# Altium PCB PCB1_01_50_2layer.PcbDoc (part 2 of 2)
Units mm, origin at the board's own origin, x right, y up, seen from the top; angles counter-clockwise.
Board outline 28.45 x 21.72 mm, 2 copper layers (Top Layer, Bottom Layer); 0 components, 1 nets, 10 pads, 74 vias.
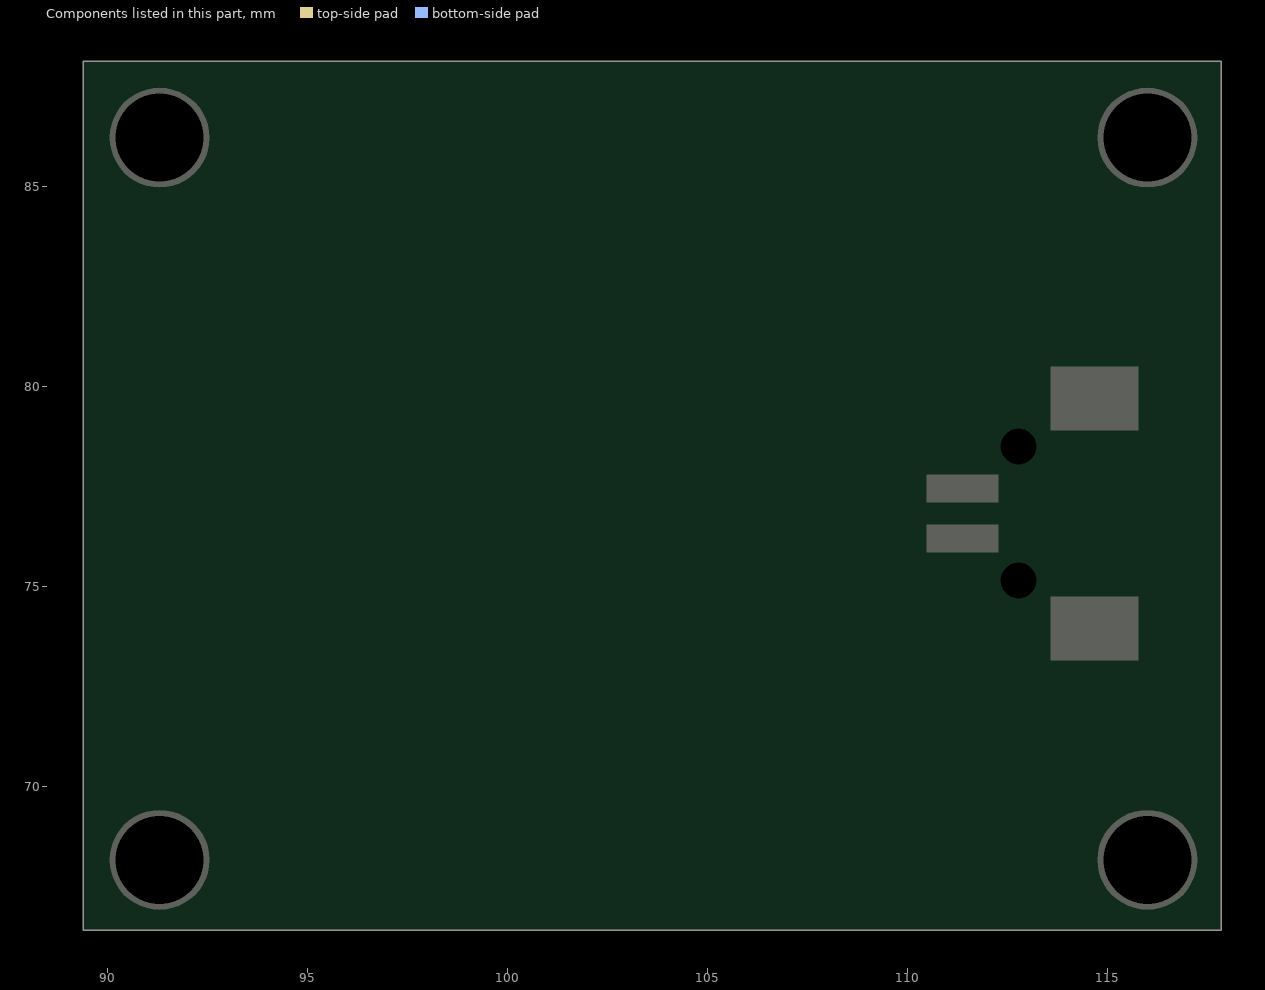
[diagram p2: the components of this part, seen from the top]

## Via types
v1: diameter 0.5, hole 0.3, Top Layer to Bottom Layer, tented both sides, 67 vias
v2: diameter 1, hole 0.5, Top Layer to Bottom Layer, 7 vias

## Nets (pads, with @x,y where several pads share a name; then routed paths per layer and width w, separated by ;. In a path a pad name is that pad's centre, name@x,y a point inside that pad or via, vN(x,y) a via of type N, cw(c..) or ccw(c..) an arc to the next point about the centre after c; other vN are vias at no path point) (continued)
copper on no net: (continued)
  Bottom Layer w0.1: 98.93,82.919 cw(c100.29,77.385) 100.643,83.073 cw(c100.265,77.417) 102.321,82.699 cw(c100.207,77.234) 103.819,81.848 cw(c100.429,77.508) 104.991,80.593 cw(c100.185,77.352) 105.731,79.038 cw(c100.25,77.359) 105.982,77.336 cw(c100.268,77.406) 104.93,74.101 cw(c100.411,77.273) 103.737,72.866 cw(c100.317,77.429) 102.22,72.053 cw(c100.294,77.457) 100.53,71.726 cw(c100.315,77.169) 98.824,71.929 cw(c100.397,77.486) 97.255,72.64 cw(c100.257,77.291) 95.974,73.785 cw(c100.333,77.32) 95.108,75.272 cw(c100.253,77.331) 94.873,78.661 cw(c100.419,77.267) 95.54,80.249 cw(c100.266,77.374) 96.65,81.561 cw(c100.247,77.355) 98.115,82.462 cw(c100.275,77.387) 101.498,82.765 cw(c100.214,77.249) 103.096,82.124 cw(c100.304,77.377) 104.424,81.032 cw(c100.313,77.421) 105.342,79.578 cw(c100.323,77.383) 105.671,76.198 cw(c100.195,77.443) 105.036,74.598 cw(c100.319,77.356) 103.946,73.268 cw(c100.363,77.347) 102.491,72.353 cw(c100.328,77.332) 99.11,72.041 ; 98.93,82.919 ccw(c100.322,77.204) 97.334,82.271 ccw(c100.145,77.496) 96.007,81.18 ccw(c100.39,77.284) 95.064,79.739 ccw(c100.332,77.298) 94.58,78.088 ccw(c100.164,77.34) 94.614,76.37 ccw(c100.366,77.349) 96.14,73.327 ccw(c100.327,77.378) 97.505,72.28 ccw(c100.387,77.462) 99.116,71.671 ccw(c100.326,77.324) 102.505,71.969 ccw(c100.34,77.391) 103.991,72.836 ccw(c100.383,77.298) 105.151,74.105 ccw(c100.277,77.404) 106.162,77.356 ccw(c100.249,77.358) 105.913,79.058 ccw(c100.173,77.347) 105.189,80.621 ccw(c100.446,77.522) 104.042,81.9 ccw(c100.212,77.242) 102.568,82.793 ccw(c100.25,77.362) 100.904,83.231 ccw(c100.285,77.464) 99.187,83.159 ccw(c100.289,77.299) 96.159,81.599 ccw(c100.324,77.331) 95.114,80.232 ccw(c100.412,77.269) 94.495,78.625 ccw(c100.249,77.332) 94.739,75.23 ccw(c100.366,77.336) 95.567,73.721 ccw(c100.203,77.236) 96.796,72.519 ccw(c100.363,77.421) 100.004,71.37 ccw(c100.311,77.335) 101.717,71.53 ccw(c100.276,77.523) 103.32,72.163 ccw(c100.454,77.224) 104.674,73.221 ccw(c100.238,77.413) 105.668,74.627 ccw(c100.214,77.438) 106.234,76.253 ccw(c100.523,77.372) 106.312,77.97 ccw(c100.151,77.338) 105.899,79.643 ccw(c100.259,77.392) 105.041,81.135 ccw(c100.384,77.463) 103.792,82.316 ccw(c100.241,77.299) 100.573,83.437 ccw(c100.293,77.376) 98.86,83.272 ccw(c100.327,77.189) 97.256,82.641 ccw(c100.15,77.49) 95.896,81.59 ccw(c100.356,77.309) 94.888,80.194 ccw(c100.403,77.272) 94.299,78.576 ccw(c100.253,77.333) 94.566,75.179 ccw(c100.376,77.34) 95.384,73.664 ccw(c100.182,77.216) 96.595,72.444 ccw(c100.403,77.497) 98.1,71.604 ccw(c100.345,77.32) 99.774,71.206 ccw(c100.315,77.265) 101.491,71.296 ccw(c100.308,77.43) 104.536,72.832 ccw(c100.308,77.359) 105.619,74.17 ccw(c100.162,77.459) 106.301,75.753 ccw(c100.505,77.371) 106.522,77.457 ccw(c100.234,77.354) 106.258,79.159 ccw(c100.157,77.342) 105.547,80.728 ccw(c100.334,77.426) 103,82.992 ccw(c100.225,77.285) 101.363,83.528 ccw(c100.287,77.583) 99.645,83.59 ccw(c100.323,77.203) 97.971,83.18 ccw(c100.275,77.298) 96.469,82.339 ccw(c100.166,77.471) 95.259,81.117 ccw(c100.445,77.253) 94.423,79.61 ccw(c100.268,77.312) 94.019,77.937 ccw(c100.189,77.343) 94.093,76.219 ccw(c100.393,77.359) 95.574,73.144 ccw(c100.273,77.315) 96.881,72.026 ccw(c100.354,77.392) 100.137,71.004 ccw(c100.306,77.36) 101.848,71.191 ccw(c100.272,77.534) 103.452,71.824 ccw(c100.45,77.229) 104.824,72.86 ccw(c100.268,77.389) 105.864,74.232 ccw(c100.169,77.456) 106.508,75.831 ccw(c100.531,77.369) 106.7,77.539 ccw(c100.221,77.351) 106.422,79.239 ccw(c100.153,77.341) 105.709,80.808 ccw(c100.345,77.437) 103.185,83.101 ccw(c100.215,77.259) 101.559,83.673 ccw(c100.278,77.422) 98.157,83.44 ccw(c100.302,77.244) 96.617,82.667 ccw(c100.119,77.523) 95.343,81.513 ccw(c100.417,77.27) 94.419,80.058 ccw(c100.365,77.284) 93.902,78.415 ccw(c100.066,77.344) 93.843,76.697 ccw(c100.457,77.38) 94.241,75.02 ccw(c100.384,77.343) 95.057,73.502 ccw(c100.154,77.19) 96.246,72.26 ccw(c100.399,77.491) 97.722,71.371 ccw(c100.366,77.393) 99.376,70.891 ccw(c100.315,77.146) 101.096,70.87 ccw(c100.275,77.527) 102.765,71.299 ccw(c100.327,77.42) 104.268,72.14 ccw(c100.455,77.224) 105.492,73.348 ccw(c100.159,77.461) 106.361,74.837 ccw(c100.282,77.418) 106.822,76.496 ccw(c100.499,77.372) 106.826,78.216 ccw(c100.126,77.329) 106.384,79.882 ccw(c100.247,77.388) 105.534,81.38 ccw(c100.431,77.508) 104.32,82.598 ccw(c100.197,77.213) 102.829,83.463 ccw(c100.24,77.339) 101.17,83.923 ccw(c100.287,77.559) 99.45,83.929 ccw(c100.329,77.182) 97.782,83.492 ccw(c100.274,77.297) 96.281,82.648 ccw(c100.143,77.496) 95.055,81.442 ccw(c100.443,77.255) 94.177,79.958 ccw(c100.334,77.292) 93.702,78.303 ccw(c100.08,77.344) 93.675,76.583 ccw(c100.469,77.384) 94.091,74.91 ccw(c100.382,77.341) 94.912,73.396 ccw(c100.144,77.182) 96.096,72.149 ccw(c100.398,77.489) 97.564,71.245 ccw(c100.375,77.418) 99.21,70.736 ccw(c100.313,77.108) 100.928,70.671 ccw(c100.279,77.508) 102.61,71.047 ccw(c100.302,77.469) 104.145,71.83 ccw(c100.494,77.18) 105.424,72.98 ccw(c100.191,77.441) 106.369,74.421 ccw(c100.205,77.444) 106.928,76.051 ccw(c100.384,77.381) 106.729,79.46 ccw(c100.154,77.342) 106,81.022 ccw(c100.482,77.551) 104.901,82.344 ccw(c100.244,77.285) 103.497,83.343 ccw(c100.201,77.224) 101.89,83.966 ccw(c100.291,77.603) 100.181,84.163 ccw(c100.306,77.298) 98.476,83.916 ccw(c100.331,77.176) 96.883,83.257 ccw(c100.142,77.497) 95.509,82.222 ccw(c100.315,77.344) 94.444,80.869 ccw(c100.463,77.245) 93.742,79.293 ccw(c100.138,77.336) 93.455,77.597 ccw(c100.272,77.352) 93.61,75.883 ccw(c100.394,77.356) 95.137,72.823 ccw(c100.246,77.288) 96.424,71.681 ccw(c100.38,77.453) 99.633,70.496 ccw(c100.314,77.202) 101.353,70.542 ccw(c100.267,77.55) 103.012,71.011 ccw(c100.336,77.409) 104.506,71.868 ccw(c100.467,77.21) 105.734,73.073 ccw(c100.159,77.46) 106.627,74.548 ccw(c100.236,77.434) 107.138,76.193 ccw(c100.57,77.368) 107.22,77.911 ccw(c100.163,77.337) 106.873,79.6 ccw(c100.158,77.345) 106.129,81.155 ccw(c100.366,77.454) 103.625,83.478 ccw(c100.196,77.212) 102.024,84.117 ccw(c100.289,77.587) 100.318,84.344 ccw(c100.302,77.334) 98.609,84.136 ccw(c100.338,77.157) 96.996,83.523 ccw(c100.179,77.445) 95.584,82.54 ccw(c100.255,77.394) 94.462,81.234 ccw(c100.393,77.28) 93.303,78.015 ccw(c100.145,77.345) 93.351,76.295 ccw(c100.496,77.392) 93.814,74.634 ccw(c100.366,77.33) 94.658,73.132 ccw(c100.135,77.174) 95.846,71.889 ccw(c100.397,77.49) 97.305,70.969 ccw(c100.388,77.453) 98.939,70.421 ccw(c100.323,77.254) 102.352,70.584 ccw(c100.273,77.535) 103.934,71.271 ccw(c100.475,77.2) 105.3,72.317 ccw(c100.287,77.37) 106.367,73.669 ccw(c100.247,77.421) 107.408,76.928 ccw(c100.392,77.367) 107.305,78.646 ccw(c100.161,77.34) 105.912,81.774 ccw(c100.443,77.518) 104.696,82.99 ccw(c100.196,77.209) 103.219,83.881 ccw(c100.22,77.281) 101.577,84.403 ccw(c100.28,77.447) 98.165,84.199 ccw(c100.328,77.183) 96.588,83.501 ccw(c100.121,77.523) 95.226,82.449 ccw(c100.317,77.344) 94.161,81.096 ccw(c100.361,77.291) 93.107,77.84 ccw(c100.192,77.348) 93.197,76.121 ccw(c100.509,77.396) 93.689,74.467 ccw(c100.351,77.32) 94.551,72.976 ccw(c100.135,77.175) 95.746,71.738 ccw(c100.399,77.493) 97.204,70.818 ccw(c100.393,77.463) 98.835,70.259 ccw(c100.323,77.228) 102.252,70.368 ccw(c100.265,77.556) 103.85,71.017 ccw(c100.444,77.243) 105.249,72.02 ccw(c100.341,77.325) 106.364,73.331 ccw(c100.195,77.442) 107.554,76.542 ccw(c100.512,77.37) 107.546,78.263 ccw(c100.118,77.326) 107.134,79.938 ccw(c100.179,77.357) 106.351,81.473 ccw(c100.366,77.453) 103.826,83.778 ccw(c100.188,77.196) 102.23,84.434 ccw(c100.284,77.558) 100.53,84.7 ccw(c100.297,77.397) 98.814,84.551 ccw(c100.316,77.223) 95.706,83.114 ccw(c100.141,77.501) 94.494,81.893 ccw(c100.453,77.251) 93.596,80.42 ccw(c100.396,77.27) 93.056,78.783 ccw(c100.175,77.336) 93.183,75.366 ccw(c100.504,77.395) 93.83,73.766 ccw(c100.194,77.22) 94.825,72.362 ccw(c100.254,77.302) 96.125,71.233 ccw(c100.394,77.481) 99.317,69.991 ccw(c100.312,77.099) 101.038,69.958 ccw(c100.274,77.519) 102.723,70.325 ccw(c100.283,77.517) 104.282,71.061 ccw(c100.504,77.166) 105.626,72.135 ccw(c100.273,77.379) 106.682,73.496 ccw(c100.229,77.43) 107.756,76.749 ccw(c100.457,77.368) 107.699,78.469 ccw(c100.098,77.32) 107.251,80.135 ccw(c100.197,77.367) 106.443,81.658 ccw(c100.361,77.446) 103.898,83.943 ccw(c100.185,77.191) 102.303,84.6 ccw(c100.282,77.549) 100.604,84.877 ccw(c100.296,77.423) 98.887,84.749 ccw(c100.325,77.2) 95.748,83.374 ccw(c100.101,77.544) 94.501,82.189 ccw(c100.428,77.267) 93.555,80.747 ccw(c100.443,77.252) 92.951,79.131 ccw(c100.043,77.347) 92.73,77.425 ccw(c100.298,77.359) 92.912,75.712 ccw(c100.434,77.371) 94.375,72.614 ccw(c100.149,77.19) 95.594,71.399 ccw(c100.406,77.508) 97.06,70.489 ccw(c100.398,77.475) 98.689,69.923 ccw(c100.308,77.064) 100.4,69.742 ccw(c100.295,77.395) 102.109,69.959 ccw(c100.297,77.471) 105.179,71.482 ccw(c100.443,77.231) 106.372,72.722 ccw(c100.138,77.47) 107.26,74.201 ccw(c100.2,77.449) 107.802,75.838 ccw(c100.61,77.364) 107.96,77.551 ccw(c100.243,77.348) 107.723,79.258 ccw(c100.198,77.358) 106.171,82.313 ccw(c100.416,77.487) 104.921,83.497 ccw(c100.186,77.189) 103.436,84.375 ccw(c100.212,77.263) 101.797,84.91 ccw(c100.281,77.509) 98.377,84.819 ccw(c100.301,77.254) 95.322,83.266 ccw(c100.168,77.476) 94.137,82.018 ccw(c100.469,77.243) 93.254,80.536 ccw(c100.402,77.266) 92.713,78.899 ccw(c99.989,77.352) 92.552,77.186 ccw(c100.352,77.366) 92.782,75.478 ccw(c100.416,77.362) 94.309,72.409 ccw(c100.164,77.206) 95.544,71.21 ccw(c100.412,77.518) 97.016,70.31 ccw(c100.399,77.476) 98.646,69.748 ccw(c100.308,77.06) 100.357,69.562 ccw(c100.296,77.38) 102.068,69.765 ccw(c100.287,77.493) 105.163,71.238 ccw(c100.484,77.189) 106.386,72.449 ccw(c100.158,77.458) 107.316,73.902 ccw(c100.158,77.465) 107.914,75.52 ccw(c100.562,77.368) 108.141,77.226 ccw(c100.328,77.358) 107.98,78.941 ccw(c100.139,77.333) 106.587,82.075 ccw(c100.508,77.576) 105.413,83.333 ccw(c100.221,77.244) 103.988,84.304 ccw(c100.183,77.186) 102.388,84.95 ccw(c100.28,77.549) 100.69,85.233 ccw(c100.295,77.458) 98.971,85.13 ccw(c100.345,77.135) 97.311,84.659 ccw(c100.291,77.252) 95.791,83.846 ccw(c100.19,77.442) 93.465,81.334 ccw(c100.495,77.229) 92.758,79.76 ccw(c100.203,77.319) 92.404,78.074 ccw(c100.099,77.348) 92.435,76.353 ccw(c100.495,77.394) 92.836,74.675 ccw(c100.465,77.376) 93.582,73.119 ccw(c100.103,77.148) 94.645,71.766 ccw(c100.294,77.354) 95.982,70.68 ccw(c100.398,77.489) 99.189,69.464 ccw(c100.309,77.052) 100.909,69.405 ccw(c100.278,77.493) 102.604,69.721 ccw(c100.261,77.57) 104.197,70.386 ccw(c100.441,77.253) 105.607,71.374 ccw(c100.399,77.27) 106.765,72.648 ccw(c100.117,77.481) 107.628,74.143 ccw(c100.205,77.449) 108.159,75.783 ccw(c100.626,77.363) 108.321,77.497 ccw(c100.264,77.35) 108.106,79.207 ccw(c100.157,77.341) 106.638,82.306 ccw(c100.493,77.562) 105.442,83.544 ccw(c100.21,77.227) 104.005,84.498 ccw(c100.183,77.187) 102.401,85.133 ccw(c100.281,77.559) 100.702,85.413 ccw(c100.296,77.467) 98.982,85.314 ccw(c100.346,77.134) 97.319,84.855 ccw(c100.301,77.231) 95.788,84.061 ccw(c100.063,77.589) 94.466,82.959 ccw(c100.337,77.334) 93.412,81.595 ccw(c100.417,77.267) 92.256,78.366 ccw(c100.012,77.349) 92.222,76.645 ccw(c100.453,77.385) 92.555,74.953 ccw(c100.513,77.397) 93.23,73.364 ccw(c100.189,77.212) 94.221,71.957 ccw(c100.21,77.258) 95.494,70.797 ccw(c100.425,77.542) 96.985,69.928 ccw(c100.398,77.467) 98.622,69.385 ccw(c100.307,77.04) 100.333,69.202 ccw(c100.296,77.365) 102.046,69.391 ccw(c100.275,77.525) 105.176,70.797 ccw(c100.537,77.131) 106.445,71.96 ccw(c100.203,77.426) 107.44,73.368 ccw(c100.106,77.487) 108.127,74.952 ccw(c100.417,77.394) 108.469,76.64 ccw(c100.512,77.366) 108.44,78.361 ccw(c100.108,77.321) 108.051,80.042 ccw(c100.115,77.33) 107.329,81.609 ccw(c100.472,77.546) 106.296,82.986 ccw(c100.351,77.41) 104.992,84.111 ccw(c100.169,77.158) 103.48,84.945 ccw(c100.214,77.278) 101.833,85.453 ccw(c100.283,77.535) 98.408,85.383 ccw(c100.322,77.201) 95.297,83.935 ccw(c100.071,77.577) 94.041,82.759 ccw(c100.411,77.282) 93.056,81.342 ccw(c100.496,77.228) 92.379,79.755 ccw(c100.176,77.322) 92.042,78.066 ccw(c100.091,77.349) 92.073,76.344 ccw(c100.495,77.395) 92.459,74.663 ccw(c100.493,77.388) 93.177,73.094 ccw(c100.14,77.175) 94.201,71.71 ccw(c100.238,77.29) 95.496,70.574 ccw(c100.432,77.555) 96.999,69.725 ccw(c100.395,77.457) 98.641,69.197 ccw(c100.306,77.025) 100.353,69.022 ccw(c100.295,77.366) 102.066,69.212 ccw(c100.271,77.537) 105.207,70.596 ccw(c100.408,77.275) 107.512,73.132 ccw(c100.197,77.446) 108.622,76.379 ccw(c100.593,77.366) 108.649,78.1 ccw(c100.148,77.329) 108.32,79.793 ccw(c100.075,77.313) 107.66,81.388 ccw(c100.382,77.483) 106.692,82.812 ccw(c100.437,77.504) 105.446,84.001 ccw(c100.188,77.189) 103.981,84.913 ccw(c100.186,77.198) 102.364,85.516 ccw(c100.285,77.596) 100.662,85.775 ccw(c100.298,77.465) 98.943,85.672 ccw(c100.348,77.128) 97.276,85.224 ccw(c100.313,77.203) 95.733,84.454 ccw(c100.074,77.576) 94.382,83.386 ccw(c100.283,77.38) 93.283,82.059 ccw(c100.469,77.243) 91.976,78.884 ccw(c100.117,77.34) 92.047,75.459 ccw(c100.475,77.385) 93.461,72.331 ccw(c100.055,77.105) 94.612,71.051 ccw(c100.354,77.437) 96.004,70.033 ccw(c100.392,77.469) 99.247,68.91 ccw(c100.308,77.043) 100.968,68.868 ccw(c100.275,77.496) 102.665,69.177 ccw(c100.252,77.597) 104.27,69.814 ccw(c100.403,77.313) 105.712,70.755 ccw(c100.49,77.18) 106.928,71.974 ccw(c100.155,77.457) 107.876,73.416 ccw(c100.112,77.485) 108.522,75.017 ccw(c100.463,77.387) 108.836,76.71 ccw(c100.501,77.365) 108.794,78.432 ccw(c100.1,77.318) 108.407,80.113 ccw(c100.096,77.322) 107.699,81.687 ccw(c100.441,77.525) 106.693,83.085 ccw(c100.4,77.464) 105.421,84.246 ccw(c100.177,77.17) 103.94,85.133 ccw(c100.189,77.209) 102.316,85.714 ccw(c100.289,77.624) 100.611,85.958 ccw(c100.299,77.456) 98.892,85.846 ccw(c100.35,77.122) 97.225,85.397 ccw(c100.317,77.195) 95.679,84.633 ccw(c100.079,77.569) 94.32,83.576 ccw(c100.261,77.399) 93.204,82.263 ccw(c100.511,77.221) 92.366,80.753 ccw(c100.405,77.261) 91.838,79.111 ccw(c99.965,77.353) 91.65,77.4 ccw(c100.277,77.362) 91.815,75.685 ccw(c100.51,77.399) 93.119,72.507 ccw(c100.052,77.104) 94.214,71.179 ccw(c100.298,77.365) 95.557,70.098 ccw(c100.417,77.527) 98.74,68.81 ccw(c100.318,77.159) 102.167,68.866 ccw(c100.266,77.552) 105.318,70.234 ccw(c100.444,77.239) 107.681,72.717 ccw(c100.145,77.468) 108.918,75.921 ccw(c100.475,77.374) 108.811,79.348 ccw(c100.117,77.327) 107.404,82.481 ccw(c100.408,77.487) 104.896,84.818 ccw(c100.194,77.208) 101.682,86.029 ccw(c100.285,77.521) 98.256,85.901 ccw(c100.331,77.176) 95.129,84.481 ccw(c100.174,77.462) 92.797,81.968 ccw(c100.452,77.25) 91.587,78.753 ccw(c100.133,77.342) 91.708,75.327 ccw(c100.487,77.389) 93.116,72.194 ccw(c100.188,77.222) 95.616,69.847 ccw(c100.413,77.517) 98.821,68.612 ccw(c100.317,77.169) 102.249,68.7 ccw(c100.265,77.556) 105.398,70.071 ccw(c100.456,77.225) 107.78,72.538 ccw(c100.127,77.476) 109.064,75.725 ccw(c100.674,77.359) 109.222,77.439 ccw(c100.301,77.349) 109.038,79.153 ccw(c100.085,77.315) 107.727,82.329 ccw(c100.553,77.613) 106.641,83.665 ccw(c100.324,77.373) 105.313,84.763 ccw(c100.175,77.166) 102.156,86.121 ccw(c100.296,77.693) 100.446,86.322 ccw(c100.304,77.419) 98.729,86.183 ccw(c100.355,77.107) 97.065,85.721 ccw(c100.319,77.188) 95.518,84.957 ccw(c100.082,77.564) 94.15,83.911 ccw(c100.229,77.429) 93.013,82.616 ccw(c100.507,77.224) 92.14,81.127 ccw(c100.457,77.242) 91.56,79.502 ccw(c100.044,77.342) 91.302,77.799 ccw(c100.152,77.354) 91.383,76.079 ccw(c100.525,77.404) 91.789,74.401 ccw(c100.515,77.396) 92.499,72.828 ccw(c100.174,77.196) 93.493,71.421 ccw(c100.161,77.21) 94.744,70.237 ccw(c100.415,77.53) 96.2,69.309 ccw(c100.434,77.556) 97.802,68.667 ccw(c100.336,77.209) 99.493,68.339 ccw(c100.307,77.092) 101.215,68.349 ccw(c100.266,77.531) 102.908,68.686 ccw(c100.248,77.609) 104.509,69.33 ccw(c100.398,77.327) 105.959,70.262 ccw(c100.536,77.131) 107.199,71.456 ccw(c100.184,77.434) 108.19,72.868 ccw(c100.177,77.456) 109.313,76.115 ccw(c100.676,77.361) 109.389,77.835 ccw(c100.211,77.337) 109.135,79.541 ccw(c100.112,77.326) 107.712,82.669 ccw(c100.43,77.508) 105.229,85.034 ccw(c100.179,77.174) 102.045,86.328 ccw(c100.299,77.728) 100.332,86.504 ccw(c100.307,77.392) 98.616,86.345 ccw(c100.358,77.097) 96.956,85.871 ccw(c100.317,77.189) 95.411,85.102 ccw(c100.078,77.568) 94.042,84.057 ccw(c100.22,77.438) 92.9,82.767 ccw(c100.505,77.225) 92.016,81.284 ccw(c100.475,77.234) 91.417,79.666 ccw(c100.083,77.335) 91.131,77.967 ccw(c100.095,77.353) 91.179,76.245 ccw(c100.504,77.4) 91.547,74.559 ccw(c100.545,77.408) 92.217,72.968 ccw(c100.241,77.241) 93.167,71.531 ccw(c100.089,77.138) 94.375,70.304 ccw(c100.386,77.487) 95.795,69.323 ccw(c100.399,77.479) 99.046,68.211 ccw(c100.304,76.975) 100.766,68.134 ccw(c100.281,77.442) 102.473,68.382 ccw(c100.265,77.558) 105.612,69.781 ccw(c100.472,77.207) 108.01,72.234 ccw(c100.101,77.488) 109.363,75.394 ccw(c100.631,77.364) 109.578,77.102 ccw(c100.403,77.357) 109.464,78.822 ccw(c100.057,77.305) 109.036,80.494 ccw(c100.089,77.322) 108.314,82.062 ccw(c100.438,77.527) 107.317,83.467 ccw(c100.453,77.516) 106.07,84.655 ccw(c100.191,77.189) 104.623,85.595 ccw(c100.16,77.14) 103.029,86.26 ccw(c100.255,77.457) 101.344,86.622 ccw(c100.297,77.7) 99.623,86.658 ccw(c100.329,77.23) 97.922,86.373 ccw(c100.329,77.176) 94.809,84.916 ccw(c100.149,77.489) 92.448,82.426 ccw(c100.496,77.229) 91.132,79.25 ccw(c99.947,77.354) 90.932,77.54 ccw(c100.218,77.36) 91.059,75.822 ccw(c100.552,77.412) 91.496,74.151 ccw(c100.511,77.392) 92.224,72.586 ccw(c100.159,77.184) 93.223,71.183 ccw(c100.147,77.198) 94.47,69.995 ccw(c100.411,77.526) 95.916,69.052 ccw(c100.445,77.58) 97.507,68.382 ccw(c100.35,77.271) 99.19,68.011 ccw(c100.305,76.996) 100.911,67.962 ccw(c100.276,77.47) 102.615,68.232 ccw(c100.266,77.555) 105.744,69.654 ccw(c100.476,77.203) 108.142,72.108 ccw(c100.092,77.493) 109.517,75.26 ccw(c100.605,77.368) 109.754,76.966 ccw(c100.448,77.359) 109.667,78.686 ccw(c100.072,77.308) 109.27,80.367 ccw(c100.061,77.309) 108.583,81.95 ccw(c100.378,77.487) 107.623,83.381 ccw(c100.519,77.582) 106.414,84.607 ccw(c100.219,77.23) 104.998,85.594 ccw(c100.193,77.213) 101.76,86.746 ccw(c100.287,77.563) 98.33,86.655 ccw(c100.352,77.12) 95.144,85.359 ccw(c100.06,77.59) 93.782,84.306 ccw(c100.215,77.445) 92.638,83.017 ccw(c100.507,77.225) 91.741,81.542 ccw(c100.501,77.223) 91.118,79.932 ccw(c100.141,77.323) 90.793,78.24 ccw(c99.997,77.353) 90.788,76.518 ccw(c100.455,77.391) 91.095,74.82 ccw(c100.48,77.384) 92.573,71.716 ccw(c100.161,77.199) 95.058,69.35 ccw(c100.436,77.566) 98.221,68 ccw(c100.31,77.038) 99.928,67.769 ccw(c100.302,77.212) 101.649,67.858 ccw(c100.251,77.589) 103.33,68.253 ccw(c100.25,77.605) 104.916,68.935 ccw(c100.422,77.295) 106.353,69.885 ccw(c100.546,77.119) 107.59,71.083 ccw(c100.188,77.429) 108.593,72.487 ccw(c100.134,77.474) 109.794,75.709 ccw(c100.552,77.371) 109.774,79.14 ccw(c100.029,77.297) 109.306,80.803 ccw(c100.103,77.329) 108.558,82.358 ccw(c100.468,77.55) 107.546,83.752 ccw(c100.453,77.514) 106.295,84.936 ccw(c100.19,77.186) 104.851,85.881 ccw(c100.152,77.124) 103.264,86.562 ccw(c100.244,77.415) 101.585,86.954 ccw(c100.3,77.764) 99.865,87.033 ccw(c100.322,77.289) 98.156,86.801 ccw(c100.35,77.123) 94.984,85.47 ccw(c100.046,77.607) 93.628,84.409 ccw(c100.22,77.442) 92.488,83.117 ccw(c100.511,77.223) 91.59,81.642 ccw(c100.509,77.219) 90.96,80.035 ccw(c100.159,77.319) 90.623,78.345 ccw(c99.96,77.354) 90.599,76.623 ccw(c100.432,77.388) 90.883,74.921 ccw(c100.508,77.395) 92.302,71.789 ccw(c100.008,77.066) 93.402,70.464 ccw(c100.265,77.332) 94.724,69.358 ccw(c100.448,77.59) 96.222,68.498 ccw(c100.429,77.537) 97.844,67.908 ccw(c100.327,77.144) 99.541,67.613 ccw(c100.305,77.085) 101.264,67.63 ccw(c100.263,77.53) 102.959,67.952 ccw(c100.275,77.539) 106.06,69.437 ccw(c100.473,77.203) 108.442,71.908 ccw(c100.078,77.5) 109.837,75.053 ccw(c100.567,77.375) 110.103,76.755 ccw(c100.524,77.36) 110.057,78.477 ccw(c100.103,77.314) 109.71,80.168 ccw(c100.022,77.295) 109.079,81.776 ccw(c100.281,77.427) 108.182,83.248 ccw(c100.437,77.511) 105.68,85.599 ccw(c100.161,77.139) 102.521,86.96 ccw(c100.289,77.654) 100.817,87.21 ccw(c100.3,77.555) 99.095,87.148 ccw(c100.348,77.146) 97.407,86.788 ccw(c100.363,77.081) 95.803,86.146 ccw(c100.223,77.351) 94.337,85.24 ccw(c100.001,77.659) 93.057,84.088 ccw(c100.346,77.338) 91.999,82.725 ccw(c100.518,77.218) 90.649,79.561 ccw(c99.998,77.346) 90.403,77.856 ccw(c100.111,77.356) 90.468,76.134 ccw(c100.516,77.404) 90.829,74.446 ccw(c100.575,77.418) 91.471,72.843 ccw(c100.299,77.275) 92.376,71.376 ccw(c99.982,77.045) 93.526,70.095 ccw(c100.311,77.4) 94.886,69.035 ccw(c100.455,77.611) 98.045,67.673 ccw(c100.335,77.128) 99.749,67.417 ccw(c100.322,77.169) 101.471,67.468 ccw(c100.286,77.504) 103.16,67.816 ccw(c100.284,77.523) 104.768,68.446 ccw(c100.421,77.253) 106.243,69.343 ccw(c100.623,76.97) 107.536,70.492 ccw(c100.131,77.431) 108.611,71.856 ccw(c99.896,77.6) 109.877,74.548 110.259,74.93 v2@110.871,74.93 ; 99.11,72.041 cw(c100.388,77.467) 97.515,72.69 cw(c100.289,77.326) 96.2,73.796 cw(c100.308,77.307) 95.305,75.264 cw(c100.26,77.33) 95.056,78.648 cw(c100.418,77.267) 95.739,80.229 cw(c100.242,77.394) 96.877,81.516 cw(c100.269,77.319) 98.37,82.37 cw(c100.308,77.253) 100.055,82.719 cw(c100.265,77.355) 103.314,81.772 cw(c100.374,77.457) 104.555,80.585 cw(c100.222,77.368) 105.347,79.058 cw(c100.238,77.359) 105.623,77.36 cw(c100.424,77.379) 105.333,75.667 cw(c100.182,77.45) 104.52,74.15 cw(c100.438,77.246) 103.268,72.975 cw(c100.292,77.478) 101.699,72.267 cw(c100.313,77.349) 99.99,72.092 cw(c100.339,77.318) 98.317,72.486 cw(c100.38,77.451) 96.854,73.392 cw(c100.183,77.218) 95.768,74.722 cw(c100.449,77.377) 95.169,76.335 cw(c100.191,77.338) 95.12,78.052 cw(c100.348,77.295) 95.64,79.691 cw(c100.336,77.317) 96.656,81.078 cw(c100.212,77.412) 98.072,82.05 cw(c100.275,77.369) 101.443,82.408 cw(c100.216,77.251) 103.03,81.744 cw(c100.337,77.418) 104.314,80.603 cw(c100.249,77.381) 105.144,79.097 cw(c100.227,77.358) 105.442,77.404 cw(c100.422,77.378) 105.157,75.711 cw(c100.189,77.446) 104.332,74.201 cw(c100.439,77.244) 103.056,73.053 cw(c100.287,77.489) 101.466,72.394 cw(c100.319,77.29) 99.752,72.294 cw(c100.356,77.382) 98.103,72.78 cw(c100.348,77.401) 96.704,73.779 cw(c100.245,77.268) 95.728,75.192 cw(c100.283,77.33) 95.405,78.562 cw(c100.411,77.271) 96.106,80.134 cw(c100.211,77.42) 97.288,81.379 cw(c100.296,77.271) 98.827,82.146 cw(c100.291,77.34) 100.532,82.358 cw(c100.266,77.402) 102.205,81.97 cw(c100.231,77.279) 103.655,81.045 cw(c100.263,77.374) 105.216,78.041 cw(c100.466,77.376) 105.147,76.327 cw(c100.203,77.439) 104.49,74.737 cw(c100.37,77.316) 103.337,73.466 cw(c100.313,77.43) 101.811,72.675 cw(c100.31,77.386) 100.108,72.446 cw(c100.335,77.31) 98.433,72.827 cw(c100.37,77.433) 96.987,73.756 cw(c100.216,77.248) 95.958,75.13 cw(c100.298,77.33) 95.572,78.489 cw(c100.406,77.274) 96.273,80.06 cw(c100.204,77.426) 97.47,81.288 cw(c100.303,77.257) 99.028,82.016 cw(c100.284,77.388) 100.739,82.162 cw(c100.251,77.343) 102.39,81.689 cw(c100.262,77.328) 103.776,80.674 cw(c100.323,77.422) 104.708,79.232 cw(c100.2,77.354) 105.079,77.553 cw(c100.43,77.376) 104.827,75.856 cw(c100.341,77.356) 101.058,72.681 cw(c100.321,77.212) 99.343,72.726 cw(c100.379,77.45) 97.756,73.387 cw(c100.248,77.275) 96.509,74.565 cw(c100.395,77.357) 95.773,76.118 cw(c100.266,77.34) 95.636,77.829 cw(c100.328,77.304) 96.134,79.473 cw(c100.307,77.335) 97.184,80.832 cw(c100.26,77.343) 98.659,81.71 cw(c100.296,77.295) 100.351,82.004 cw(c100.273,77.425) 102.031,81.654 cw(c100.236,77.29) 103.474,80.722 cw(c100.362,77.448) 104.47,79.325 cw(c100.188,77.351) 104.893,77.66 cw(c100.437,77.375) 104.672,75.959 cw(c100.332,77.371) 97.624,73.697 cw(c100.213,77.242) 96.464,74.959 cw(c100.425,77.369) 95.858,76.567 cw(c100.17,77.337) 95.892,78.281 cw(c100.391,77.281) 96.571,79.859 cw(c100.203,77.425) 97.786,81.068 cw(c100.309,77.246) 99.372,81.729 cw(c100.279,77.463) 101.087,81.749 cw(c100.23,77.278) 102.682,81.113 cw(c100.353,77.441) 103.92,79.927 cw(c100.199,77.354) 104.611,78.354 cw(c100.39,77.38) 104.659,76.641 cw(c100.229,77.426) 104.042,75.038 cw(c100.378,77.312) 102.867,73.79 cw(c100.299,77.457) 101.297,73.093 cw(c100.324,77.27) 99.584,73.046 cw(c100.37,77.431) 97.983,73.669 cw(c100.252,77.276) 96.746,74.854 cw(c100.405,77.362) 96.067,76.432 cw(c100.2,77.335) 96.048,78.145 cw(c100.381,77.286) 96.703,79.733 cw(c100.207,77.421) 97.919,80.94 cw(c100.309,77.246) 99.515,81.573 cw(c100.28,77.48) 101.228,81.535 cw(c100.225,77.27) 102.79,80.822 cw(c100.282,77.383) 104.378,76.226 cw(c100.214,77.434) 103.583,74.704 cw(c100.405,77.279) 102.25,73.629 cw(c100.296,77.466) 100.595,73.171 cw(c100.32,77.248) 98.9,73.416 cw(c100.367,77.423) 97.44,74.318 cw(c100.263,77.286) 96.473,75.732 cw(c100.368,77.351) 96.15,77.417 cw(c100.266,77.325) 96.544,79.085 cw(c100.312,77.328) 97.574,80.456 cw(c100.277,77.319) 99.076,81.282 cw(c100.281,77.381) 100.783,81.433 cw(c100.243,77.309) 102.401,80.864 cw(c100.339,77.429) 103.647,79.689 cw(c100.199,77.353) 104.296,78.101 cw(c100.316,77.383) 103.472,74.854 cw(c100.4,77.285) 102.143,73.776 cw(c100.3,77.455) 100.482,73.345 cw(c100.324,77.278) 98.798,73.649 cw(c100.348,77.391) 97.388,74.626 cw(c100.319,77.323) 96.527,76.106 cw(c100.288,77.337) 96.359,77.811 cw(c100.349,77.3) 96.934,79.426 cw(c100.222,77.403) 98.131,80.649 cw(c100.271,77.348) 101.444,81.103 cw(c100.233,77.289) 102.929,80.246 cw(c100.336,77.426) 103.898,78.835 cw(c100.259,77.37) 104.176,77.145 cw(c100.29,77.401) 103.69,75.502 cw(c100.353,77.339) 102.548,74.227 cw(c100.33,77.377) 99.255,73.677 cw(c100.369,77.427) 97.759,74.513 cw(c100.265,77.29) 96.785,75.92 cw(c100.337,77.343) 96.52,77.611 cw(c100.323,77.311) 97.034,79.245 cw(c100.234,77.39) 98.211,80.486 cw(c100.304,77.258) 99.82,81.075 cw(c100.281,77.463) 101.519,80.887 cw(c100.245,77.311) 102.962,79.963 cw(c100.289,77.394) 103.831,78.489 cw(c100.335,77.381) 103.953,76.783 cw(c100.313,77.389) 101.984,74.099 cw(c100.306,77.437) 100.319,73.701 cw(c100.333,77.332) 98.658,74.11 cw(c100.296,77.319) 97.363,75.227 cw(c100.312,77.326) 96.894,78.517 cw(c100.342,77.304) 97.824,79.954 cw(c100.273,77.332) 99.316,80.79 cw(c100.277,77.376) 102.561,80.09 cw(c100.341,77.427) 103.563,78.706 cw(c100.28,77.376) 103.803,77.013 cw(c100.308,77.393) 101.934,74.275 cw(c100.308,77.431) 100.269,73.881 cw(c100.337,77.351) 98.621,74.335 cw(c100.274,77.295) 97.388,75.516 cw(c100.39,77.356) 96.875,77.148 cw(c100.25,77.333) 97.215,78.821 cw(c100.268,77.356) 98.319,80.125 cw(c100.3,77.272) 99.92,80.724 cw(c100.28,77.432) 101.607,80.466 cw(c100.28,77.367) 102.956,79.418 cw(c100.224,77.361) 103.61,77.839 cw(c100.384,77.379) 103.401,76.146 cw(c100.299,77.387) 102.382,74.775 cw(c100.333,77.368) 99.119,74.295 cw(c100.331,77.359) 97.748,75.313 cw(c100.373,77.352) 97.082,76.886 cw(c100.224,77.336) 97.302,78.576 cw(c100.291,77.336) 98.348,79.924 cw(c100.297,77.281) 99.939,80.546 cw(c100.279,77.42) 101.62,80.263 cw(c100.294,77.386) 103.459,77.539 cw(c100.333,77.385) 103.076,75.878 cw(c100.36,77.336) 101.886,74.658 cw(c100.311,77.424) 100.231,74.242 cw(c100.333,77.347) 97.505,76.062 cw(c100.32,77.336) 97.258,77.748 cw(c100.349,77.302) 97.954,79.306 cw(c100.254,77.37) 99.374,80.245 cw(c100.274,77.409) 101.076,80.274 cw(c100.251,77.326) 102.525,79.376 cw(c100.251,77.37) 103.247,77.832 cw(c100.364,77.38) 103.01,76.148 cw(c100.339,77.358) 101.888,74.868 cw(c100.311,77.423) 100.244,74.422 cw(c100.331,77.342) 97.596,76.315 cw(c100.274,77.33) 97.493,78.013 cw(c100.334,77.307) 98.366,79.474 cw(c100.289,77.308) 99.914,80.18 cw(c100.278,77.404) 101.587,79.879 cw(c100.317,77.413) 102.786,78.677 cw(c100.312,77.386) 102.34,75.468 cw(c100.333,77.367) 99.165,74.862 cw(c100.296,77.313) 97.926,76.022 cw(c100.292,77.329) 98.359,79.219 cw(c100.269,77.351) 101.541,79.7 cw(c100.319,77.413) 102.693,78.456 cw(c100.31,77.386) 102.848,76.768 cw(c100.327,77.374) 100.332,74.781 cw(c100.338,77.37) 98.732,75.34 cw(c100.31,77.327) 98.037,78.455 cw(c100.252,77.368) 99.258,79.626 cw(c100.272,77.372) 100.945,79.75 cw(c100.27,77.362) 102.319,78.762 cw(c100.306,77.388) 101.971,75.608 cw(c100.316,77.401) 100.407,74.962 cw(c100.319,77.326) 98.343,78.626 cw(c100.27,77.35) 101.394,79.37 cw(c100.292,77.388) 102.326,76.384 cw(c100.346,77.352) 101.066,75.269 cw(c100.329,77.324) 99.385,75.355 cw(c100.297,77.315) 98.257,76.602 cw(c100.269,77.33) 98.351,78.28 cw(c100.259,77.361) 99.621,79.38 cw(c100.275,77.39) 101.292,79.221 cw(c100.304,77.397) 102.318,77.893 cw(c100.326,77.383) 102.036,76.24 cw(c100.331,77.364) 100.621,75.343 cw(c100.329,77.351) 99.011,75.808 cw(c100.326,77.337) 98.309,77.328 cw(c100.309,77.322) 99.014,78.845 cw(c100.277,77.33) 100.631,79.271 cw(c100.285,77.388) 102.038,76.617 cw(c100.336,77.362) 100.757,75.552 cw(c100.328,77.345) 99.137,75.937 cw(c100.325,77.336) 98.495,77.471 cw(c100.295,77.325) 99.375,78.88 cw(c100.27,77.364) 101.033,78.95 cw(c100.293,77.388) 102.007,77.61 cw(c100.303,77.388) 101.406,76.069 cw(c100.331,77.369) 99.78,75.775 cw(c100.312,77.328) 98.7,77.021 cw(c100.296,77.329) 99.249,78.573 cw(c100.27,77.35) 100.873,78.825 cw(c100.289,77.385) 101.839,77.499 cw(c100.31,77.387) 101.069,76.056 cw(c100.331,77.35) 99.439,76.157 cw(c100.315,77.331) 98.896,77.692 cw(c100.275,77.341) 100.122,78.756 cw(c100.273,77.37) 101.533,77.965 cw(c100.308,77.386) 101.219,76.383 cw(c100.333,77.36) 99.618,76.252 cw(c100.312,77.329) 99.108,77.767 cw(c100.275,77.343) 100.484,78.566 cw(c100.282,77.382) 101.482,77.338 cw(c100.323,77.38) 100.376,76.222 99.917,76.681 99.917,77.007 v2(100.265,77.355)
  Bottom Layer w0.7: v2@110.871,74.93 v2(111.252,74.93)
  other v2: 111.252,73.406 111.252,74.168 111.252,79.375 111.252,80.137

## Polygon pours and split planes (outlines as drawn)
Net1 on Top Layer "NET1_L01_P004" (solid, pour order 4): 89.408,88.138 117.856,88.138 117.856,66.421 89.408,66.421
Net1 on Bottom Layer "NET1_L02_P001" (solid, pour order 1): 89.408,88.138 117.856,88.138 117.856,66.421 89.408,66.421

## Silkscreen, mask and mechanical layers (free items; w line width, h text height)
Top Overlay:
  lines w0.2: 112.181,74.435 112.181,74.01 113.181,74.01 ; 112.181,79.235 112.181,79.66 113.181,79.66 ; 116.431,74.01 117.181,74.01 117.181,79.66 116.431,79.66
  text "2 LAYER 50 COILS" at 106.299,67.437 h0.8
Mechanical 2:
  the board outline again, w0.1
Board Shape:
  the board outline again, w0.1
Mechanical 13:
  lines w0.1: 112.181,74.01 112.181,79.66 117.181,79.66 117.181,74.01 112.181,74.01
